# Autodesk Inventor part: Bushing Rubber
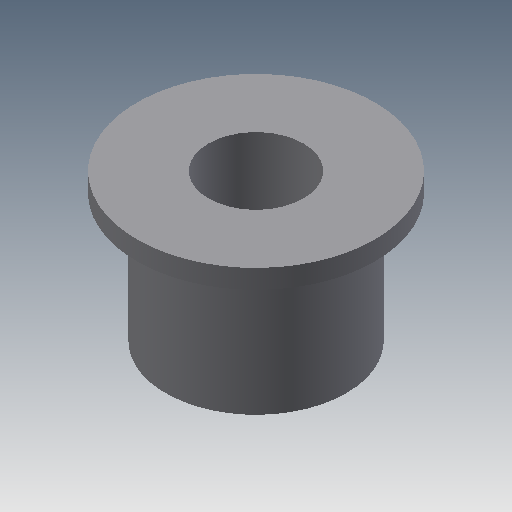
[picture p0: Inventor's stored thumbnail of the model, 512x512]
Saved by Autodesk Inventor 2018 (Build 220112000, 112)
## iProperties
Created: 2010-03
Part Number: Bushing Rubber
Document SubType Name: Modeling
Designer: bhakira
Density: 1 g/cm^3
Material: Generic
Appearance: Default
Author: bhakira
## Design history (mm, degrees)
sketch "Sketch1"
  geometry: L1 (25, 31)-(25, 27); L2 (25, 27)-(19, 27); L3 (19, 27)-(19, 0); L4 (19, 0)-(0, 0); L5 (0, 0)-(0, 31); L6 (0, 31)-(25, 31); 1 further point
  constraints: 12 end point, 1 coincident, 1 other
  dimensions: "d1" = 50 diameter of L1 L5; "d2" = 38 diameter of L3 L5; "d3" = 4 distance of L1.start L1.end; "d4" = 27 distance between parallel lines of L4 L2
revolve "Revolution1" sketch "Sketch1" stored, may be unused: angle "d5" = 90 deg
hole "Hole1" diameter "d8" = 20; stored, may be unused: countersink angle "d12" = 82 deg, drill point angle "d14" = 118 deg; dims "d6" = 10, "d7" = 10, "d9" = 6, "d10" = 34.925, "d11" = 2, "d13" = 8
body "Solid1"
